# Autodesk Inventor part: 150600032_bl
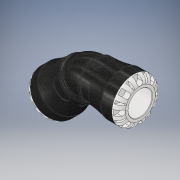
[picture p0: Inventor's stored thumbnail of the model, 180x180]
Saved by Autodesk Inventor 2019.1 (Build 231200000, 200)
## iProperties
Created: 2016-12
Part Number: 150600032_bl
Material: PVC-Piping
Description: PLASSON G-PLASS 45°  ELBOW 32-32
Document SubType Name: Modeling
Designer: KIM
Mass: 664.223 g
Surface Area: 733.008 cm^2
Volume: 474.445 cm^3
Density: 1.4 g/cm^3
Appearance: Black Cast
Author: KIM
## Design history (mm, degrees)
derived "150600.ipt"
feature "Solid1::150600.ipt" dims "ScaleForDerivedMember" = 10
tag "TaggingFeature1"
body "Solid1"
other parameters: "d1" = 23.52 [user parameter], "d2" = 32 [user parameter], "d4" = 58 [user parameter], "d8" = 49.3 [user parameter], "d13" = 7.2 [user parameter], "d14" = 7.2 [user parameter], "d15" = 0 [user parameter], "d17" = 360 deg [user parameter], "d19" = 8 deg [user parameter], "d20" = 0.64 [user parameter], "d21" = 0.64 [user parameter], "d22" = 8 deg [user parameter], "d24" = 0 [user parameter], "d26" = 360 deg [user parameter], "d33" = 5.8 [user parameter], "d43" = 45.24 [user parameter], "d51" = 0.58 [user parameter], "d54" = 11.2 [user parameter], "d55" = 7.04 [user parameter], "d57" = 14.112 [user parameter], "d58" = 0 [user parameter], "d74" = 0 [user parameter], "d77" = 2.66667 [user parameter], "d78" = 56 [user parameter], "d82" = 0.64 [user parameter], "d115" = 360 deg [user parameter], "d207" = 90 deg [user parameter], "d228" = 9.52 [user parameter], "d247" = 1.16 [user parameter], "d248" = 3.36 [user parameter], "d268" = 10.353 [user parameter], "d269" = 3.1059 [user parameter], "d270" = 69 [user parameter], "d277" = 135 deg [user parameter], "d279" = 3.1059 [user parameter], "d280" = 135 deg [user parameter], "d281" = 0 [user parameter], "d282" = 0 [user parameter], "d_" = 32 [user parameter], "E_" = 58 [user parameter], "l_" = 56 [user parameter], "A_" = 69 [user parameter], "d9" = 9 [user parameter], "d11" = 58 [user parameter]
